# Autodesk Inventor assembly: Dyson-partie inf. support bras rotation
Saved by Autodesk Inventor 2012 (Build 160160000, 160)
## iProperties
Created: 2012-11
Part Number: Dyson-partie inf. support bras rotation
Document SubType Name: Assembly
Designer: Administrateur
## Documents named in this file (11)
- F:\Dyson\SI\2_Présentation éleve\SW_AM01 complet\Composants importés\Dyson Air Multiplier-Assemblage final\Dyson-partie inf. support bras rotation.iam
- F:\Dyson\SI\2_Présentation éleve\SW_AM01 complet\Composants importés\Dyson Air Multiplier-Assemblage final\Dyson-Partie inf. base ABS marron.ipt
- F:\Dyson\SI\2_Présentation éleve\SW_AM01 complet\Composants importés\Dyson Air Multiplier-Assemblage final\Dyson-Partie inf. base grise clair.ipt
- F:\Dyson\SI\2_Présentation éleve\SW_AM01 complet\Composants importés\Dyson Air Multiplier-Assemblage final\Vis torks M2x6.ipt
- F:\Dyson\SI\2_Présentation éleve\SW_AM01 complet\Composants importés\Dyson Air Multiplier-Assemblage final\Dyson-Partie inf. tampon.ipt
- F:\Dyson\SI\2_Présentation éleve\SW_AM01 complet\Composants importés\Dyson Air Multiplier-Assemblage final\Dyson-Partie inf.axe bielle 1.ipt
- F:\Dyson\SI\2_Présentation éleve\SW_AM01 complet\Composants importés\Dyson Air Multiplier-Assemblage final\Circlps Ø3 int.ipt
- F:\Dyson\SI\2_Présentation éleve\SW_AM01 complet\Composants importés\Dyson Air Multiplier-Assemblage final\Dyson-Partie inf.bielle plastique.ipt
- F:\Dyson\SI\2_Présentation éleve\SW_AM01 complet\Composants importés\Dyson Air Multiplier-Assemblage final\Dyson-Partie inf.axe bielle 2.ipt
- F:\Dyson\SI\2_Présentation éleve\SW_AM01 complet\Composants importés\Dyson Air Multiplier-Assemblage final\Dyson-Partie inf.bielle acier.ipt
- F:\Dyson\SI\2_Présentation éleve\SW_AM01 complet\Composants importés\Dyson Air Multiplier-Assemblage final\Dyson-Partie inf. cablage prise.ipt
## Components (20 placed, 10 different names)
1. Dyson-Partie inf. base ABS marron:1
2. Dyson-Partie inf. base grise clair:1
3. Vis torks M2x6:1
4. Vis torks M2x6:2
5. Vis torks M2x6:3
6. Vis torks M2x6:4
7. Vis torks M2x6:5
8. Dyson-Partie inf. tampon:1
9. Dyson-Partie inf. tampon:6
10. Dyson-Partie inf. tampon:7
11. Dyson-Partie inf. tampon:8
12. Dyson-Partie inf. tampon:9
13. Dyson-Partie inf.axe bielle 1:1
14. Circlps Ø3 int:1
15. Circlps Ø3 int:2
16. Dyson-Partie inf.bielle plastique:2
17. Dyson-Partie inf.axe bielle 2:1
18. Circlps Ø3 int:3
19. Dyson-Partie inf.bielle acier:1
20. Dyson-Partie inf. cablage prise:1
